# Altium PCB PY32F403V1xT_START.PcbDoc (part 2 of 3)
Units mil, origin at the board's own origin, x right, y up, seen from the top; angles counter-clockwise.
Board outline 1968.43 x 4717 mil, 2 copper layers (Top Layer, Bottom Layer), stack 21 mil thick; 171 components, 201 nets, 720 pads, 402 vias.
Unrouted connection lines stored in the file: 1.
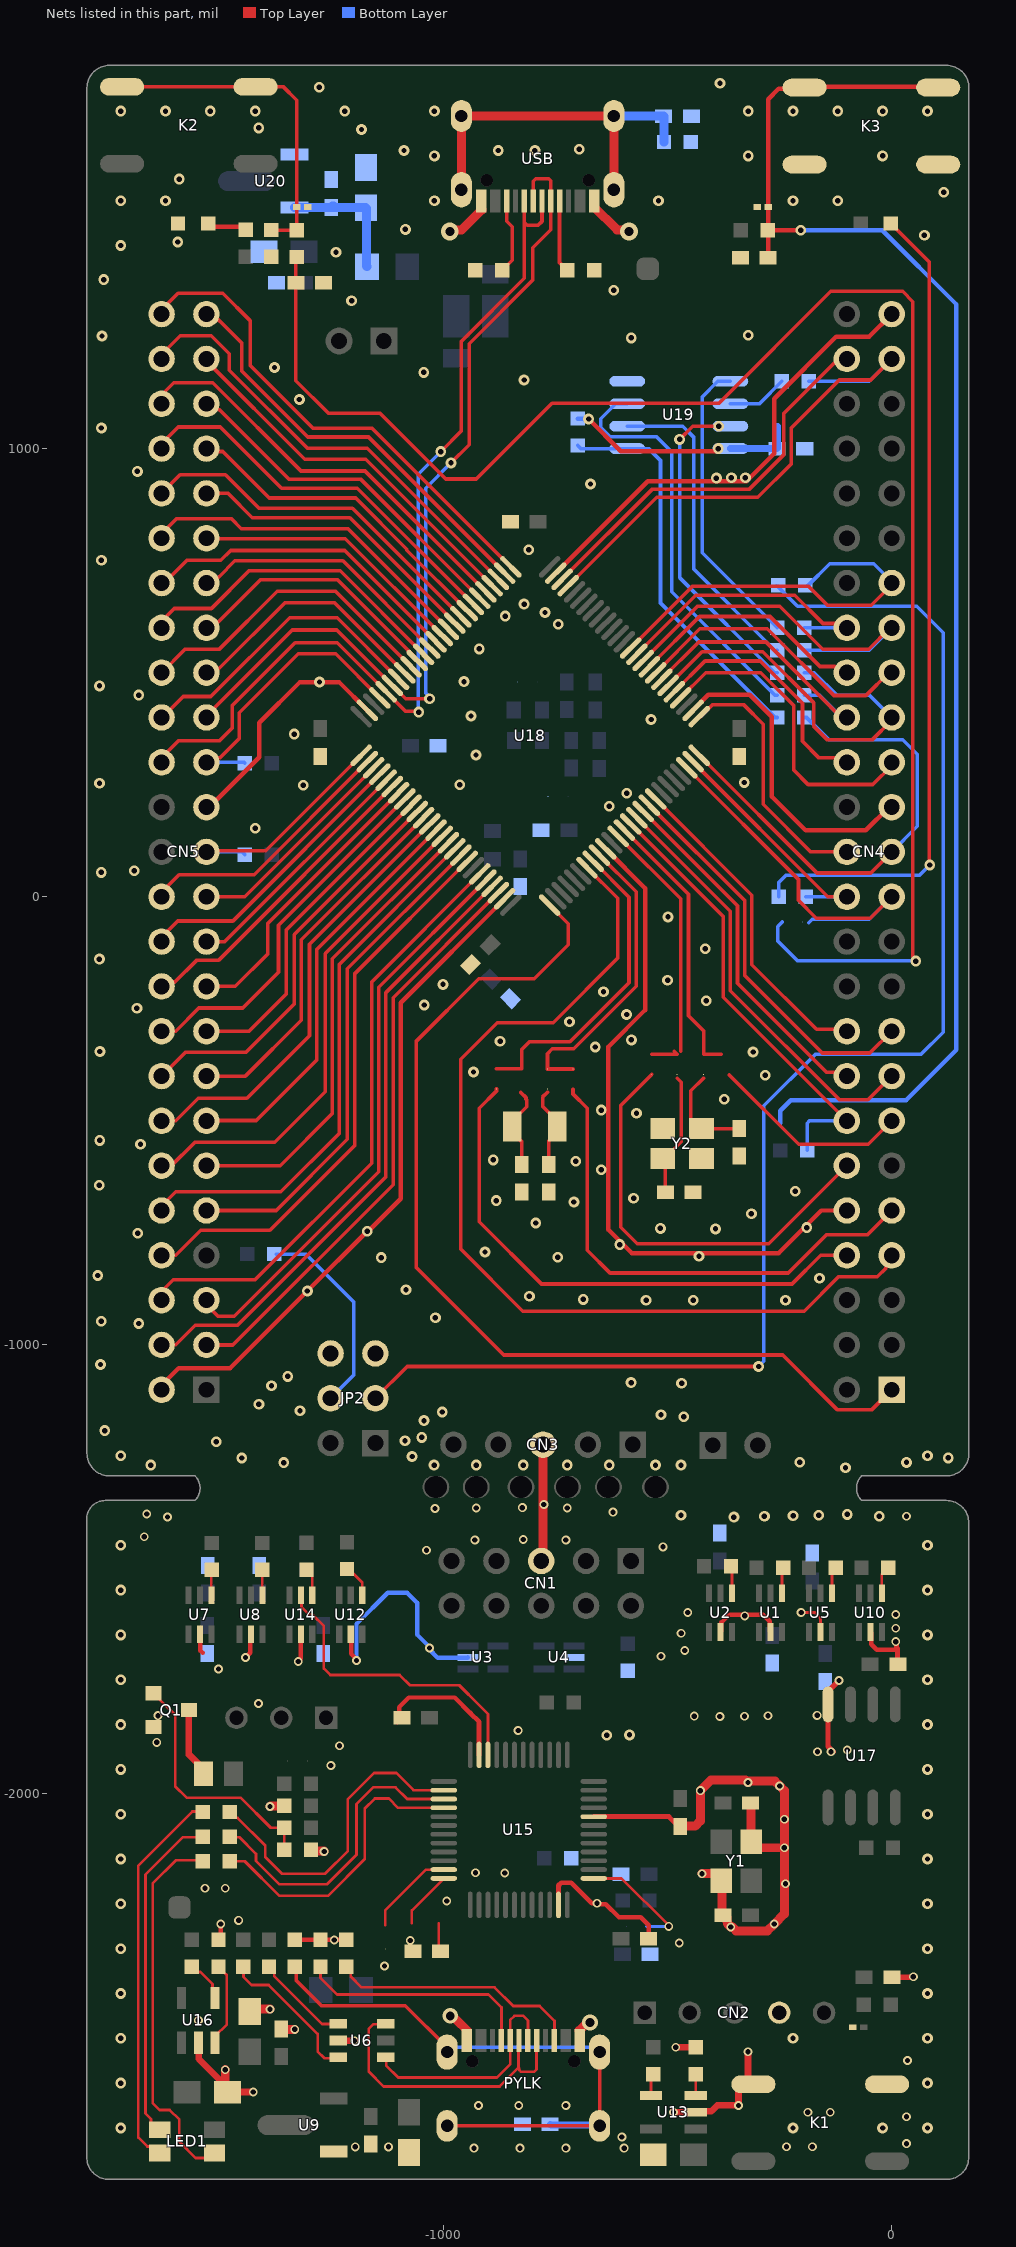
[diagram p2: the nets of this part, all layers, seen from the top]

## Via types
v1: diameter 24, hole 12, Top Layer to Bottom Layer, tented both sides, 230 vias
v2: diameter 19.68, hole 11.81, Top Layer to Bottom Layer, tented both sides, 116 vias
v3: diameter 19.68, hole 11.81, Top Layer to Bottom Layer, 37 vias
v4: diameter 35, hole 20, Top Layer to Bottom Layer, tented both sides, 11 vias
v5: diameter 40, hole 20, Top Layer to Bottom Layer, tented both sides, 6 vias
v6: diameter 30, hole 15, Top Layer to Bottom Layer, tented both sides, 2 vias

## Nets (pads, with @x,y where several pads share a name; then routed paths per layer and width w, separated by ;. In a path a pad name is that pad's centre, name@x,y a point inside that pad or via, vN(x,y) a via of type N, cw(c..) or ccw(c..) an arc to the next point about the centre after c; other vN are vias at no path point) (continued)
DIR_VCP_RX: U14.5 U15.22 | length 688.5
  Top Layer w6: U14.5@-1318.31,-1558.69 -1316.93,-1560.07 -1316.93,-1584.86 -1300.4,-1601.4 -1292.8,-1601.4 -1267,-1627.19 -1267,-1721.94 -1252.39,-1736.55 -1097.7,-1736.55 -1074.95,-1759.29 -964.82,-1759.29 -920.62,-1803.49 -900.9,-1823.21 U15.22@-900.9,-1914.68
F_CS: R47.1 R48.2 U19.1 | length 883.2
  Bottom Layer w8: R47.1@-700.5,1007 -693.5,1000 U19.1@-590,1000 -542.5,1000 -515.9,973.4 -515.9,655.34 -260.56,400 R48.2@-255,400
F_HOLD: R55.2 U19.7 | length 713.7
  Top Layer w8: v1(-473.3,1020.4) -443.8,1049.9 v1(-386,1049.9)
  Bottom Layer w8: v1(-473.3,1020.4) -473.3,712.53 -260.77,500 R55.2@-255,500
F_SCK: R49.2 U19.6 | length 135.7
  Bottom Layer w8: U19.6@-360,1100 -295,1100 R49.2@-245,1150
F_SI: R50.2 U19.5 | length 661.6
  Bottom Layer w8: U19.5@-360,1150 -387.8,1150 -422.61,1115.19 -422.61,767.61 R50.2@-255,600
F_SO: R52.2 U19.2 | length 714.4
  Bottom Layer w8: U19.2@-590,1050 -466.4,1050 -441.28,1024.88 -441.28,730.67 -260.61,550 R52.2@-255,550
F_VDD: C36.2 R46.2 R47.2 U19.8 | length 500.5
  Top Layer w10: v1(-676.21,1065.94) -604.64,994.37 -392.33,994.37 v1(-386.8,999.9)
  Bottom Layer w10: R47.2@-700.5,1067 -677.27,1067 v1(-676.21,1065.94)
  Bottom Layer w15: U19.8@-360,1000 C36.2@-256,1000 -255,1001 -255,1050
F_WP: R53.2 U19.3 | length 916.9
  Bottom Layer w8: U19.3@-590,1100 -615.7,1100 -649.25,1066.45 -649.25,1047.31 -627.94,1026 -524.5,1026 -491,992.5 -491,680.24 -260.76,450 R53.2@-255,450
GND: C1.1 C2.1 C3.1 C4.1 C5.1 C6.1 C7.1 C8.1 C9.1 C10.1 C11.1 C12.1 C13.1 C14.1 C15.1 C16.1 C17.1 C18.1 C19.1 C20.1 C21.1 C22.1 C23.1 C24.1 C25.1 C26.1 C27.1 C28.1 C29.1 C30.1 C31.2 C32.2 C33.2 C34.2 C35.1 C36.1 C41.1 C42.1 C43.1 C44.1 C45.1 C46.1 C47.1 C48.1 C49.1 CN1.5 CN2.4 CN3.3 CN4.10 CN4.27 CN4.49 CN5.2 CN5.27 JP2.5 JP2.6 K1.3 K1.4 K3.3 K3.4 LED_VDD*.2 PYLK.A1 PYLK.A12 PYLK.B1 PYLK.B12 Q1.2 R1.1 R3.2 R5.1 R8.2 R20.1 R21.1 R25.1 R28.2 R30.1 R33.2 R51.1 R56.1 R60.1 R61.2 R62.1 R63.1 U1.2 U2.2 U3.2 U4.2 U5.2 U6.2 U7.2 U8.2 U9.1 U10.2 U11.2 U12.2 U13.2 U14.2 U15.8 U15.23 U15.47 U16.2 U17.4 U18.10 U18.27 U18.49 U18.74 U18.99 U19.4 U20.1 U21.2 U22.2 USB.A1 USB.A12 USB.B1 USB.B12 Y1.2 Y1.4 Y2.2 Y2.4 | length 10026.1
  Top Layer w6: v2(-202,-1597) -172,-1597 -158.94,-1610.06 U5.2@-158.94,-1640.31
  Top Layer w10: CN5.2@-1639,-1100 -1590.6,-1051.6 -1475.7,-1051.6 v1(-1303.7,-879.6) v1(-1170.4,-746.3) -1167.83,-746.3 -1095.44,-673.91 -1095.44,-236.39 U18.99@-864.03,-4.98 ; U7.2@-1543.45,-1645.31 -1542.46,-1646.3 -1542.46,-1681.92 -1537.64,-1686.75 ; CN5.27@-1533.91,205.09 -1516.94,205.09 -1410.84,311.19 -1410.84,388.59 -1320.31,479.13 -1233.12,479.13 U18.74@-1169.82,415.82 ; R30.1@-1502,-2327 -1497,-2322 v2(-1497,-2292) ; C16.1@-1487,-2652 -1487,-2662 C16.1@-1482,-2667 ; v2(-1442,-1697.4) -1431.11,-1686.51 -1431.11,-1646.68 U8.2@-1429.74,-1645.31 ; C2.1@-1432,-2487 C2.1@-1427,-2482 ; C3.1@-1362,-2526 C3.1@-1361,-2527 ; R8.2@-1332,-2327 v2@-1243.05,-2327 ; v2(-1324.1,-1706.3) -1318.41,-1700.61 U14.2@-1318.41,-1645.41 ; R20.1@-1295.48,-2126.12 R20.1@-1293.96,-2124.6 ; v2(-1243.9,-2327.85) v2@-1243.05,-2327 ; R3.2@-1217,-2327 v2@-1243.05,-2327 ; U12.2@-1206.88,-1645.31 -1205.59,-1646.6 -1205.59,-1689.38 -1195.17,-1699.8 -1195.17,-1705.17 v2@-1197,-1707 ; C21.1@-1103.64,-1842 -1093.64,-1832 C21.1@-1093,-1832 -1099.05,-1825.95 -1099.05,-1807.86 -1077.77,-1786.58 -975.02,-1786.58 -940.18,-1821.42 ; C17.1@-1068.41,-2352.5 C17.1@-1067.41,-2351.5 ; PYLK.A1@-953.69,-2552.11 PYLK.B12@-941.88,-2552.11 ; U18.49@-749.46,722.05 -544.41,927.1 -323.94,927.1 -262.21,988.83 -262.21,1111.26 -123.46,1250 -50,1250 CN4.49@0,1300 ; PYLK.B1@-701.72,-2552.11 PYLK.A12@-689.91,-2552.11 ; v2@-657.53,-2248.44 v2@-657.4,-2248.31 ; v2@-655.39,-2247.98 -637.64,-2247.98 -608.43,-2277.2 -559.93,-2277.2 -542.09,-2295.05 C20.1@-542.13,-2324.41 ; U18.10@-638.1,106.82 -550.31,19.02 -550.31,-252.67 -632,-334.36 -632,-743.04 -580.04,-795 -251.97,-795 -156.97,-700 CN4.10@-100,-700 ; U18.27@-443.23,416.79 -409.01,451 -317,451 -267.67,401.67 -267.67,223.66 -192.25,148.24 -57.76,148.24 -6,200 CN4.27@0,200 ; U2.2@-382.74,-1641.25 U2.2@-381.79,-1640.31 -379.9,-1638.42 -379.9,-1619.05 -362.85,-1602 v2@-326.98,-1602 ; v2(-327.8,-1604.4) -326.98,-1603.58 v2@-326.98,-1602 ; U1.2@-270.36,-1640.31 -272.25,-1638.42 -272.25,-1616.75 -287,-1602 v2@-326.98,-1602 ; U10.2@-47.51,-1640.31 -45.62,-1642.2 -45.62,-1668.04 -33.39,-1680.28 13.04,-1680.28
  Top Layer w11: -940.18,-1821.42 -920.58,-1841.02 U15.23@-920.58,-1914.68 ; U15.47@-743.42,-2249.32 -743.42,-2206.09 -737.26,-2199.93 -714.92,-2199.93 -669.13,-2245.72 v2(-657.65,-2245.72) ; U15.8@-664.68,-2052.47 -497.06,-2052.47 -475.53,-2074 C22.1@-471.88,-2074
  Top Layer w12: Q1.2@-1646.8,-1852.2 Q1.2@-1641.99,-1857.01 ; v2(-135.29,-1907.73) -130.16,-1907.73 -142,-1895.89 U17.4@-142,-1802 -142,-1773.12 -117.61,-1748.73 v2(-117.61,-1748.49) ; C6.1@0.2,-2410.8 47.2,-2410.8 v2(48.4,-2409.6) ; v2(9.2,-1662) 10.67,-1663.47 10.67,-1675.47 13.04,-1677.84 13.04,-1680.28 13.04,-1711.04 C18.1@14,-1712
  Top Layer w15: U16.2@-1547.52,-2557.52 -1546.09,-2558.96 -1546.09,-2592.91 C16.1@-1487,-2652 ; C16.1@-1482,-2667 v2(-1424.44,-2667) ; U6.2@-1226.34,-2551.95 -1224.76,-2553.53 -1223.71,-2552.48 v2(-1198.92,-2552.48) ; v2(-487,-2712) U13.2@-437,-2712 -434.84,-2709.84 -402.34,-2709.84 -388.77,-2696.26 v2@-342.74,-2696.26 ; v2(-482,-2567) R25.1@-437,-2567 ; v2(-342,-2697) -342,-2652.56 -330.74,-2641.3 -320.45,-2641.3 v2(-320.45,-2577)
  Top Layer w20: C16.1@-1487,-2652 v2(-1487,-2617) ; C2.1@-1427,-2482 v2(-1387,-2482) ; v2(-1387.17,-2029.71) -1386.41,-2028.96 -1355.83,-2028.96 R21.1@-1355.07,-2028.2 ; C3.1@-1361,-2527 v2(-1332,-2527) ; R20.1@-1293.96,-2124.6 -1293.96,-2124.88 -1289.48,-2129.36 -1267.06,-2129.36 v2(-1266.3,-2130.13) ; v4(-984.92,-2497) -980.87,-2497 -973.37,-2504.5 -972.28,-2504.5 -946.1,-2530.69 PYLK.B12@-946.1,-2531.04 ; v5@-981.85,1482.73 -976.76,1487.83 -959.25,1487.83 -914.31,1532.77 USB.B1@-914.31,1533.34 ; CN1.5@-782,-1482 CN1.5@-774.53,-1474.53 ; CN1.5@-777.74,-1477.74 CN3.3@-777.74,-1222.44 ; PYLK.B1@-697.5,-2530.08 -680.26,-2512.84 -674.34,-2512.84 v4(-673.29,-2511.8) ; USB.B12@-665.71,1540.9 -612.63,1487.83 -589.97,1487.83 v5(-586.15,1484) ; C22.1@-476.88,-2065 -471.88,-2070 C22.1@-471.88,-2074 -471.59,-2073.72 -438.59,-2073.72 -426.88,-2062 v2(-426.88,-1994.43) -403.05,-1970.59 -326.59,-1970.59 v2(-320.74,-1976.45) -319.65,-1976.45 -316.55,-1973.35 -260.53,-1973.35 v2(-249.97,-1983.9) -239.42,-1994.46 v2(-239.42,-2058.15) -239.42,-2121.87 -239.42,-2269.54 v2(-261.88,-2292) -277.15,-2307.27 -347.11,-2307.27 v2@-357.36,-2297.02 ; v2(-423.02,-2179.71) -395.94,-2179.71 Y1.2@-380.34,-2195.31 -378.61,-2197.04 -378.61,-2270.27 C19.1@-376.88,-2272 -372.88,-2272 -367.88,-2277 -367.88,-2286.5 -366.63,-2287.75 ; -366.63,-2291.37 v2(-359.17,-2298.82) ; C25.1@-314.88,-2022 -314.15,-2022.73 -314.15,-2107.96 Y1.4@-313.41,-2108.69 -300.26,-2121.84 v2(-239.45,-2121.84)
  Bottom Layer w6: v2@-1197.74,-1704.17 v2(-1194.11,-1704.17)
  Bottom Layer w10: v2(-1194.11,-1704.17) -1194.11,-1622.51 -1124.54,-1552.94 -1081.28,-1552.94 -1059,-1575.22 -1059,-1646.21 -1031.11,-1674.1 v2(-1031.11,-1676.11) ; v2@-1032,-1679 -1013.28,-1697.72 -946.19,-1697.72 U3.2@-945.46,-1697
  Bottom Layer w20: CN1.5@-782,-1482 CN1.5@-776,-1476 ; CN3.3@-777.74,-1222.44 CN3.3@-776,-1224.18 ; CN3.3@-776,-1222.44 CN3.3@-776,-1219.06
  other v1: -1720.22,-2747 -220.22,-2747 -20.22,-2747 79.78,-2747 -1720.22,-2647 79.78,-2647 -1720.22,-2547 -220.22,-2547 79.78,-2547 -1720.22,-2447 79.78,-2447 -1720.22,-2347 79.78,-2347 -1720.22,-2247 79.78,-2247 -1720.22,-2147 79.78,-2147 -1720.22,-2047 79.78,-2047 -1720.22,-1947 79.78,-1947 -636,-1871 -585,-1870 -1720.22,-1847 79.78,-1847 -1720.22,-1747 79.78,-1747 -1720.22,-1647 79.78,-1647 -1720.22,-1547 79.78,-1547 -1720.22,-1447 79.78,-1447 -352,-1384 -284,-1382 -28,-1382 -220,-1381 -470,-1380 -163,-1380 -99,-1378 -103,-1274 -1653.43,-1268 -1021,-1268 -927,-1268 -822,-1268 -724,-1268 -630,-1268 -527,-1268 -470,-1268 -1356.5,-1262.4 -205.3,-1261.87 33,-1262 -1450,-1252.1 126,-1252 -1070,-1249 -1720.22,-1247 79.78,-1247 -1507.1,-1216.1 -1085.9,-1213.5 -1048.3,-1206.3 -1756,-1191 -1043.4,-1168.8 -463.91,-1160.44 -514.6,-1155.9 -1002.7,-1149.6 -1320.22,-1147 -1411.9,-1132.5 -1383.7,-1090.8 -468.71,-1085.34 -581.51,-1084.04 -1347.6,-1070.2 -1765.2,-1043.5 -1680,-952 -1763.9,-947.1 -1018,-939.5 -548,-900.49 -443,-900.49 -236.91,-900.49 -688.3,-898.3 -808.3,-891.1 -1083.6,-876.8 -161,-851 -1771.4,-845 -1138.7,-805.1 -744.97,-804.36 -429.9,-801.9 -907.4,-792.6 -607,-776 -1682,-751 -393,-741 -516,-740 -189.7,-738.2 -794.1,-727.9 -313,-707 -709.07,-681.16 -882.57,-677.86 -575.8,-672.4 -215,-657 -1768,-643.8 -648,-609 -705.17,-590.26 -889.17,-587.06 -1676,-552 -1767,-543.6 -569.3,-483.1 -648,-476 -373.8,-451.7 -282.3,-398 -933.2,-391.1 -309.2,-346.3 -1766.7,-345.2 -661.6,-335.3 -873.7,-322.3 -580.8,-319.4 -719,-279 -591.5,-262.6 -1684,-249 -1043.1,-241.4 -414,-232 -643,-212 -1001.1,-195.6 -500,-186 -1767.8,-139 -416,-116 -499,-45 -1763.7,54.4 -1690,58 -1420.22,153 -630.1,202.1 -591.4,231.1 -1313,249 -963.7,249.7 -1767.4,253.4 -329,255 -927.4,316.4 -1333,363 -536.85,395.59 -938.6,403.2 -1680,450 -1767.4,470.5 -1276.72,479.13 -954.3,480.1 -920.22,553 -744.1,608.3 -862.1,626.2 -773.5,634.2 -820.22,653 -1763.3,751.1 -810,774 -672,921 -391.1,934.1 -357.6,934.7 -326.45,934.81 -1683,949 -1763.3,1045.9 -1321.51,1109.49 -820.22,1153 -1043.9,1170 -1377,1181 -580.95,1246.89 -1761.9,1251.2 -320.22,1253 -1205,1330 -620.22,1353 -1758,1377 -1239.9,1438.1 -1720.22,1453 -1593,1461 73,1476 -1085,1489 -1720.22,1553 -1620.22,1553 -1020.22,1553 -520.22,1553 -220.22,1553 -120.22,1553 116,1572 -1589.4,1601.2 -1020.22,1653 -320.22,1653 -20.22,1653 -1088,1665 -878,1665 -796,1665 -697,1668 -1183,1712 -1412.2,1715.5 -1720.22,1753 -1620.22,1753 -1520.22,1753 -1420.22,1753 -1220.22,1753 -1020.22,1753 -320.22,1753 -220.22,1753 -120.22,1753 -20.22,1753 79.78,1753 -1277,1806 -383,1815
  other v2: -932,-2792 -829.5,-2792 -727,-2792 -597,-2792 -234.75,-2789 -177,-2789 33,-2782 -602,-2767 33,-2722 -187,-2712 -137,-2712 -922,-2697 -832,-2697 -727,-2697 35.4,-2596.4 -1547,-2507 -1532,-2212 -1487,-2212 -236.88,-2202 -1639.7,-1886.66 -1637,-1827 -514.65,-1694.43 -455.06,-1597.05 -1038,-1458 -930,-1435 -727,-1435 -822,-1434 -1616,-1384 33,-1382 -1662,-1377 -622,-1373 -1019,-1365 -927,-1364 -724,-1364 -824,-1363 -776,-1356
  other v3: -1196.77,-2789.27 -1122.52,-2789.28 -1131.7,-2385.8 -473.95,-2334.23 -1074.25,-2328.85 -1457.07,-2283.82 -992.57,-2240.41 -863.37,-2178.06 -928.53,-2177.5 -1251.29,-1938.32 -165.67,-1907.47 -99.24,-1903.62 -1232.14,-1894.38 -833.45,-1860.42 -383.41,-1828.94 -328.42,-1828.55 -440.34,-1828.16 -275.76,-1827.37 -166.33,-1826.45 -1413,-1800 -1502,-1723 -461.71,-1681.53 -469.81,-1643.1 9.2,-1632.22 9.2,-1601.35 -510.41,-1450.46 -1667.7,-1427.9
  other v5: -986,1484
L_USB_CN_DM: PYLK.A7 PYLK.B7 U6.4 | length 509.8
  Top Layer w6: U6.4@-1128.85,-2589.4 -1127.82,-2590.43 -1127.82,-2607.54 -1100.96,-2634.4 -880.64,-2634.4 -850.93,-2604.7 PYLK.B7@-850.93,-2552.51 ; PYLK.B7@-851.42,-2552.02 -851.42,-2506.42 -842,-2497 -822,-2497 -811.31,-2507.69 -811.31,-2551.46 PYLK.A7@-811.96,-2552.11
L_USB_CN_DP: PYLK.A6 PYLK.B6 U6.6 | length 674.3
  Top Layer w6: U6.6@-1128.85,-2514.6 -1129.74,-2515.49 -1156.61,-2515.49 -1166.65,-2525.53 -1166.65,-2621.6 -1133.78,-2654.47 -874.73,-2654.47 -834.45,-2614.19 -832.05,-2611.79 ; -832.54,-2612.28 -832.54,-2553.01 PYLK.A6@-831.64,-2552.11 ; -831.25,-2617.39 -831.25,-2614.19 ; -830.69,-2617.96 -826.95,-2621.69 -797.94,-2621.69 -792.7,-2616.45 -792.7,-2552.54 PYLK.B6@-792.27,-2552.11
LED_BLUE: R9.2 U15.28 | length 674.3
  Top Layer w6: R9.2@-1477,-2152 -1443.49,-2152 -1366.3,-2229.19 -1257.44,-2229.19 -1175.67,-2147.42 -1175.67,-2034.59 -1153.08,-2012 -1122,-2012 -1101.21,-2032.79 U15.28@-999.32,-2032.79
LED_GREEN: R6.2 U15.26 | length 726.2
  Top Layer w6: R6.2@-1477,-2042 -1464,-2055 -1459.6,-2055 -1397.73,-2116.87 -1397.73,-2142.73 -1360.59,-2179.87 -1264.73,-2179.87 -1213.52,-2128.66 -1213.52,-2013.52 -1155.25,-1955.25 -1105.09,-1955.25 -1066.93,-1993.42 U15.26@-999.32,-1993.42
LED_RED: R4.2 U15.27 | length 697.6
  Top Layer w6: R4.2@-1477,-2097 -1475.6,-2098.4 -1455.51,-2098.4 -1418.4,-2135.52 -1418.4,-2150.95 -1365.78,-2203.57 -1260.48,-2203.57 -1194.32,-2137.41 -1194.32,-2024.32 -1157,-1987 -1107,-1987 -1080.9,-2013.1 U15.27@-999.32,-2013.1
NetC1_2: C1.2 PYLK.1 PYLK.2 PYLK.3 PYLK.4 R8.1 | length 1406.9
  Top Layer w8: R8.1@-1332,-2387 -1328.71,-2390.29 -1328.71,-2418.13 -1272.36,-2474.48 -1085.03,-2474.48 -991.88,-2567.63 PYLK.1@-991.88,-2577.71 ; PYLK.3@-991.88,-2742.27 PYLK.4@-651.72,-2742.27 PYLK.2@-651.72,-2577.71
  Bottom Layer w8: PYLK.1@-980.96,-2566.79 PYLK.2@-662.64,-2566.79
  Bottom Layer w15: C1.2@-762,-2739 -760.36,-2740.64 -653.36,-2740.64 PYLK.4@-651.72,-2742.27
  Bottom Layer w20: PYLK.1@-991.88,-2577.71 PYLK.1@-980.96,-2566.79 ; PYLK.2@-662.64,-2566.79 PYLK.2@-651.72,-2577.71
NetC17_2: C17.2 R31.2 | length 64.1
  Top Layer w6: -1010.79,-2290.25 -1010.79,-2348.12 C17.2@-1006.41,-2352.5
NetC27_2: C27.2 R38.1 Y2.3 | length 281.1
  Top Layer w8: C27.2@-504.8,-659.7 -504.8,-590.47 Y2.3@-511.11,-584.16 -507.17,-584.16 -469.45,-546.44 -469.45,-414.04 -478.8,-404.69
NetC30_2: C30.2 R41.1 Y2.1 | length 221.4
  Top Layer w8: -419.8,-404.7 -448.25,-433.15 -448.25,-492.93 -448.05,-493.13 -448.05,-497.61 -428.43,-517.24 Y2.1@-424.49,-517.24 -340.34,-517.24 C30.2@-339.8,-516.7
NetC32_1: C32.1 R44.2 Y3.1 | length 188.4
  Top Layer w8: -828,-436 -816,-448 -816,-451.28 -814.59,-452.69 -814.59,-468.6 -846.19,-500.2 -846.19,-513 -846.19,-525.79 -825,-546.98 C32.1@-825,-597
NetC35_2: C35.2 R45.2 Y3.2 | length 187.2
  Top Layer w8: -768,-436 -778.94,-446.94 -778.94,-467.07 -745.8,-500.2 -745.8,-513 -745.8,-525.79 -765,-544.99 C35.2@-765,-597
NetC45_2: C45.2 K3.1 K3.2 R57.2 R58.1 U21.1 | length 3376.6
  Top Layer w10: C45.2@-275.7,1425.3 R57.2@-275.7,1485.8 ; v1(-202.8,1487.1) -274.4,1487.1 R57.2@-275.7,1485.8 ; K3.2@105,1807.7 -193,1807.7 -198.08,1802.62 -252.38,1802.62 -275.7,1779.3 U21.1@-275.7,1539 -275.7,1488 R57.2@-276.8,1486.9 R57.2@-275.7,1485.8
  Bottom Layer w10: -248.55,-505 -248.55,-477.55 -225,-454 32,-454 144.5,-341.5 144.5,1321.5 -21.1,1487.1 v1(-202.8,1487.1)
NetC46_2: C46.2 C47.2 F2.2 U20.3 | length 296.1
  Bottom Layer w20: U20.3@-1332.51,1537.74 -1332.18,1538.07 -1250.63,1538.07 C47.2@-1250.3,1538.4 -1247.6,1541.1 -1245.6,1541.1 -1245.6,1538.7 -1245.3,1538.4 -1174.1,1538.4 C46.2@-1173,1537.3 -1171.84,1536.14 -1171.84,1407.16 F2.2@-1170.68,1406
NetC48_2: C48.2 R59.1 R70.1 | length 3773
  Top Layer w8: R70.1@-1329.6,1427.3 C48.2@-1329.6,1369.9 -1329.6,1151.51 -1256.78,1078.7 -1141.56,1078.7 -994.96,932.1 -927.1,932.1 -757.8,1101.4 -385.4,1101.4 -136,1350.8 24.4,1350.8 47.3,1327.89 47.3,-133.1 53.44,-139.23 v1(53.44,-143.56)
  Bottom Layer w8: R59.1@-244.05,-56.3 -254.25,-66.5 -254.25,-98.85 -209.9,-143.2 v1@53.08,-143.2
NetC49_2: C49.2 R63.2 USB.1 USB.2 USB.3 USB.4 | length 838.1
  Top Layer w20: USB.2@-960.08,1577.52 USB.4@-960.08,1742.08 USB.3@-619.92,1742.08 USB.1@-619.92,1577.52
  Bottom Layer w20: USB.3@-619.92,1742.08 -619.38,1741.54 -509.54,1741.54 C49.2@-509,1741 -508.5,1740.5 -508.5,1684.5 R63.2@-508,1684
NetCN4_8: CN4.8 R66.2 | length 1216.6
  Top Layer w8: R66.2@-881.8,-428.7 -881.8,-433.5 -920.1,-471.8 -920.1,-725.4 -781.5,-864 -222.43,-864 -158.43,-800 CN4.8@-100,-800
NetCN4_9: CN4.9 R67.2 | length 1130.8
  Top Layer w8: R67.2@-711.13,-429.18 -711.13,-440.07 -679.4,-471.8 -679.4,-788.5 -628.4,-839.5 -231.1,-839.5 -145.4,-753.8 -53.8,-753.8 CN4.9@0,-700
NetCN4_12: CN4.12 R68.1 | length 961.5
  Top Layer w8: R68.1@-535.3,-396.45 -604.6,-465.75 -604.6,-737.1 -567.5,-774.2 -274.2,-774.2 CN4.12@-100,-600
NetCN4_13: CN4.13 R69.1 | length 449
  Top Layer w8: R69.1@-362.9,-397 -207.5,-552.4 -52.4,-552.4 CN4.13@0,-500
NetJP2_3: JP2.3 R42.2 | length 3246.1
  Top Layer w8: JP2.3@-1152,-1119 -1081,-1048 v1(-297,-1048)
  Bottom Layer w8: v1(-297,-1048) -285.24,-1036.24 -285.24,-466.63 -170.11,-351.5 65.5,-351.5 115,-302 115,589 56,648 -210,648 -256,694 R42.2@-257.5,694
NetJP2_4: JP2.4 R43.1 | length 453.7
  Bottom Layer w8: R43.1@-1373.5,-798 -1306.2,-798 -1200.2,-904 -1200.2,-1067.2 JP2.4@-1252,-1119
NetK2_3: K2.3 K2.4 R60.2 R70.2 U22.1 | length 746.9
  Top Layer w8: K2.4@-1715,1807.7 -1358.18,1807.7 -1327.61,1777.12 U22.1@-1327.61,1539 -1327.61,1487.49 R70.2@-1327.8,1487.3 -1384.2,1487.3 R60.2@-1384.6,1487.7
NetLED1_2: LED1.2 R9.1 | length 846.1
  Top Layer w6: R9.1@-1537,-2152 -1539.33,-2149.67 -1596.67,-2149.67 -1649,-2202 -1649,-2691 -1633.2,-2706.8 -1611.14,-2706.8 -1589.47,-2728.47 -1589.47,-2777.84 -1553.18,-2814.13 -1521.92,-2814.13 LED1.2@-1510.98,-2803.18
NetLED1_3: LED1.3 R6.1 | length 884.3
  Top Layer w6: LED1.3@-1652.72,-2803.48 LED1.3@-1638.02,-2818.18 ; LED1.3@-1633.02,-2803.18 -1647.72,-2788.48 -1660.91,-2788.48 -1681,-2768.39 -1681,-2161.66 -1560.41,-2041.07 -1537.93,-2041.07 R6.1@-1537,-2042
NetLED1_4: LED1.4 R4.1 | length 755.1
  Top Layer w6: LED1.4@-1640.34,-2763.5 -1652.64,-2751.19 -1652.64,-2727.26 -1665,-2714.91 -1665,-2181.66 -1581.61,-2098.27 -1538.27,-2098.27 R4.1@-1537,-2097
NetLED_PA1_2: LED_PA1.2 R54.1 | length 1851.9
  Top Layer w8: LED_PA1.2@-2,1502 84.23,1415.77 v1@84.23,71
  Bottom Layer w8: R54.1@-252,0 -252,32 -236,48 62,48 v1(85,71)
NetLED_VDD*_1: LED_VDD*.1 R65.1 | length 89.8
  Top Layer w10: LED_VDD*.1@-1525,1502 -1518.07,1495.07 -1448.07,1495.07 R65.1@-1441,1488
NetPYLK_A5: PYLK.A5 R1.2 | length 530.1
  Top Layer w6: R1.2@-1274.51,-2387.01 -1274.51,-2412.18 -1237.49,-2449.21 -899.42,-2449.21 -870.76,-2477.87 PYLK.A5@-870.76,-2551.86
NetPYLK_B5: PYLK.B5 R3.1 | length 566.5
  Top Layer w6: R3.1@-1217,-2387 -1206.69,-2397.31 -1206.69,-2409.66 -1183.15,-2433.2 -885.89,-2433.2 -844.34,-2474.76 -785.45,-2474.76 -752.29,-2507.92 -752.29,-2551.5 PYLK.B5@-752.9,-2552.11
NetQ1_1: Q1.1 R19.1 R20.2 | length 559
  Top Layer w6: Q1.1@-1647,-1777.2 -1645.03,-1777.2 -1633.28,-1788.94 -1633.28,-1790.77 -1598.54,-1825.51 -1598.54,-1984.66 -1573.14,-2010.06 -1452.55,-2010.06 -1385.39,-2077.22 R19.1@-1355.47,-2077.22 ; R20.2@-1355.48,-2126.12 R19.1@-1355.48,-2077.23
NetQ1_3: Q1.3 R15.1 | length 166.5
  Top Layer w6: Q1.3@-1571.51,-1817.85 Q1.3@-1568.26,-1814.6 ; R15.1@-1535.46,-1957 R15.1@-1535.46,-1951.09
  Top Layer w15: Q1.3@-1568.26,-1814.6 -1568.26,-1913.72 -1535.46,-1946.51 R15.1@-1535.46,-1957
NetR2_1: R2.1 U1.4 | length 57.9
  Top Layer w6: U1.4@-244.77,-1553.69 -244.77,-1499.98 R2.1@-241.79,-1497
NetR7_1: R7.1 U2.4 | length 57.8
  Top Layer w6: R7.1@-358.94,-1497 -356.2,-1499.73 U2.4@-356.2,-1553.69
NetR10_1: R10.1 U5.4 | length 60.3
  Top Layer w6: U5.4@-133.34,-1553.69 -133.34,-1505.7 R10.1@-124.65,-1497
NetR11_1: R11.1 U6.3 | length 332.9
  Top Layer w6: R11.1@-1447,-2387 -1446.23,-2387.77 -1446.23,-2410.31 -1428.59,-2427.95 -1390.2,-2427.95 -1280.76,-2537.39 -1280.76,-2576.13 -1265.37,-2591.52 -1237.26,-2591.52 U6.3@-1235.47,-2589.72
NetR12_1: R12.1 U6.1 | length 227.7
  Top Layer w6: R12.1@-1388.25,-2382 -1377.85,-2392.4 -1377.85,-2408.32 -1271,-2515.17 U6.1@-1225.03,-2515.17
NetR13_1: R13.1 U7.4 | length 59
  Top Layer w6: R13.1@-1523.45,-1502 -1517.86,-1507.59 U7.4@-1517.86,-1558.69
NetR14_1: R14.1 U8.4 | length 60.8
  Top Layer w6: R14.1@-1416.06,-1501.98 R14.1@-1406.18,-1511.86 ; U8.4@-1404.14,-1558.69 R14.1@-1404.14,-1511.88
NetR18_1: R18.1 U10.4 | length 62.7
  Top Layer w6: U10.4@-21.92,-1553.69 -21.92,-1511.41 R18.1@-7.51,-1497
NetR22_1: R22.1 U12.4 | length 75.3
  Top Layer w6: R22.1@-1215.37,-1499.89 -1211.38,-1499.89 -1181.29,-1529.97 U12.4@-1181.29,-1558.69
NetR24_2: R24.2 U13.4 | length 49.6
  Top Layer w6: U13.4@-537,-2674.5 -537,-2632 R24.2@-532,-2627
NetR25_2: R25.2 U13.3 | length 47.5
  Top Layer w6: U13.3@-437,-2674.5 R25.2@-437,-2627
NetR26_1: R26.1 U14.4 | length 62.8
  Top Layer w6: R26.1@-1305.8,-1501.3 -1292.72,-1514.38 U14.4@-1292.72,-1558.69
NetR27_2: R27.2 U15.1 | length 262.3
  Top Layer w6: U15.1@-664.68,-2190.27 -602.82,-2190.27 -497.3,-2295.79 v3(-497.3,-2297.2)
  Bottom Layer w6: R27.2@-546.97,-2297.57 -497.67,-2297.57 v3(-497.3,-2297.2)
NetR29_2: R29.2 U16.4 | length 96.1
  Top Layer w6: R29.2@-1562,-2387 -1550,-2399 -1542.56,-2399 -1515.5,-2426.06 -1515.5,-2451 U16.4@-1509.5,-2457
NetR30_2: R30.2 U16.3 | length 188.5
  Top Layer w6: U16.3@-1509.5,-2557 -1509.5,-2542 -1483.44,-2515.94 -1483.44,-2406.32 -1490,-2399.76 -1490,-2399 R30.2@-1502,-2387
NetR31_1: R31.1 U15.36 | length 129.6
  Top Layer w6: -1070.79,-2290.25 -1070.79,-2261.74 U15.36@-999.32,-2190.27
NetR33_1: R33.1 U15.35 | length 201.4
  Top Layer w6: -1130.04,-2294.6 -1130.04,-2261.62 -1039,-2170.58 U15.35@-999.32,-2170.58
NetR61_1: R61.1 USB.A5 | length 160.6
  Top Layer w8: USB.A5@-741.21,1551.5 -741.21,1415.21 R61.1@-724,1398
NetR62_2: R62.2 USB.B5 | length 168.4
  Top Layer w8: R62.2@-869,1398 -846.51,1420.49 -846.51,1494.6 -858.9,1507 USB.B5@-858.9,1551.92
NRST: CN4.14 R40.2 R58.2 U18.14 | length 1013.9
  Top Layer w8: U18.14@-582.42,162.5 -376.03,-43.89 -376.03,-223.97 CN4.14@-100,-500
  Bottom Layer w8: R40.2@-188.55,-566 -188.55,-505 -183.55,-500 CN4.14@-100,-500
OSC_IN: R38.2 R68.2 U18.12 | length 602.3
  Top Layer w8: U18.12@-610.26,134.66 -471,-4.6 -471,-344.2 ; R68.2@-535.27,-351.67 R38.2@-478.77,-351.66 -485.34,-345.1
OSC_OUT: R41.2 R69.2 U18.13 | length 612.3
  Top Layer w8: U18.13@-596.34,148.58 -453.3,5.53 -453.3,-265.6 -419.77,-299.13 R41.2@-419.77,-351.67 -380.83,-351.67
PA0: CN4.23 R59.2 U18.23 | length 852
  Top Layer w8: U18.23@-457.15,287.77 -208,38.62 -208,-8.06 -168.34,-47.72 -47.72,-47.72 CN4.23@0,0
  Bottom Layer w8: -184.87,-57.77 -177.2,-50.1 -50.1,-50.1 CN4.23@0,0
PA1: CN4.24 R54.2 U18.24 | length 560.9
  Top Layer w8: U18.24@-443.23,301.69 -443.23,300.57 -142.66,0 CN4.24@-100,0
  Bottom Layer w8: R54.2@-192,0 CN4.24@-100,0
PA2: CN4.25 R48.1 U18.25 | length 1085.1
  Top Layer w8: U18.25@-429.31,315.61 -166.7,53 -47,53 CN4.25@0,100
  Bottom Layer w8: R48.1@-195,400 -189.94,400 -139.94,350 25,350 57,318 57,157 CN4.25@0,100
PA3: CN4.26 U18.26 | length 580.8
  Top Layer w8: U18.26@-429.31,401.91 -426.61,401.9 -400.54,427.98 -329.54,427.98 -286.84,385.27 -286.84,206.25 -180.58,100 CN4.26@-100,100
PA4: CN4.29 U18.29 | length 706.9
  Top Layer w8: U18.29@-471.06,444.11 -415.17,500 -292,500 -218.17,426.17 -218.17,282.09 -186.54,250.47 -41.97,250.47 0,292.44 CN4.29@0,300
PA5: CN4.30 U18.30 | length 556.8
  Top Layer w8: U18.30@-484.85,457.58 -416.43,526 -293,526 -199,432 -199,346.64 -162.13,309.77 -109.77,309.77 CN4.30@-100,300
PA6: CN4.31 R55.1 U18.31 | length 902.8
  Top Layer w8: U18.31@-498.55,471.5 -423.05,547 -288,547 -174.32,433.32 -174.32,381.13 -143.16,349.96 -43.74,349.96 0,393.71 CN4.31@0,400
  Bottom Layer w8: R55.1@-195,500 -172.79,500 -122.79,450 -50,450 CN4.31@0,400
PA7: CN4.32 R53.1 U18.32 | length 632.3
  Top Layer w8: U18.32@-512.83,486.1 -430.58,568.35 -280.61,568.35 -112.26,400 CN4.32@-100,400
  Bottom Layer w8: R53.1@-195,450 -161.78,450 -111.78,400 CN4.32@-100,400
PA8: CN5.34 U18.67 | length 711.8
  Top Layer w8: CN5.34@-1639,500 CN5.34@-1629,500 -1577.16,551.82 -1500.7,551.82 -1370.64,681.89 -1241.01,681.89 U18.67@-1072.38,513.26
PA9: CN5.33 U18.68 | length 582.4
  Top Layer w8: CN5.33@-1539,500 -1529.23,509.77 -1500.04,509.77 -1353.58,656.23 -1243.2,656.23 U18.68@-1086.3,499.34
PA10: CN5.32 U18.69 | length 676.4
  Top Layer w8: CN5.32@-1627.64,400 -1580.87,446.77 -1519.06,446.77 -1343.23,622.61 -1237.4,622.61 U18.69@-1100.22,485.42
PA11: CN5.31 U18.70 USB.A7 USB.B7 | length 2002.3
  Top Layer w8: CN5.31@-1528.35,404.53 -1337.58,595.3 -1237.94,595.3 U18.70@-1114.14,471.5 -1084.28,441.64 v1@-1031.36,441.64 ; v1(-983.4,968.1) -942.87,1008.63 -942.87,1234.13 -801,1376 -801,1448 -760.42,1488.58 USB.B7@-760.47,1551.92 ; USB.A7@-799.84,1551.92 -799.84,1596.16 -794,1602 -765.16,1602 -760.47,1597.31 USB.B7@-760.47,1551.92
  Bottom Layer w8: v1(-1031,442) -1031,445.84 -1039.84,454.69 -1039.84,911.66 v1(-983.4,968.1)
PA12: CN5.30 U18.71 USB.A6 USB.B6 | length 2118.2
  Top Layer w8: CN5.30@-1639,300 -1590.53,348.47 -1499.38,348.47 -1471.74,376.11 -1471.74,426.15 -1331.19,566.7 -1237.18,566.7 U18.71@-1128.06,457.58 -1084.73,414.25 v1@-1050.88,414.25 ; v1(-1006.23,993.26) -960,1039.49 -960,1239.63 -819.53,1380.1 -819.53,1504.53 ; USB.B6@-819.53,1551.92 -819.53,1504.53 ; USB.A6@-780.16,1551.92 -780.16,1506.84 -789,1498 -813,1498 -819.53,1504.53
  Bottom Layer w8: v1@-1056.64,413.84 -1056.64,942.85 v1(-1006.23,993.26)
  other v1: -1055,412
PA13: CN5.29 R37.2 U18.72 | length 648.6
  Top Layer w8: CN5.29@-1529,300 -1519.23,309.77 -1499.02,309.77 -1455.74,353.05 -1455.74,410.42 -1323.88,542.28 -1240.6,542.28 U18.72@-1141.98,443.66
  Bottom Layer w8: CN5.29@-1529,300 -1445.09,300 R37.2@-1443.09,298
PA14: CN5.25 R39.2 U18.76 | length 533
  Top Layer w8: CN5.25@-1539,100 -1536.11,102.89 -1396.45,102.89 U18.76@-1183.74,315.61
  Bottom Layer w8: CN5.25@-1529,100 -1449.09,100 R39.2@-1443.09,94
PA15: CN5.24 U18.77 | length 606.5
  Top Layer w8: CN5.24@-1639,0 -1590,49 -1422.51,49 U18.77@-1169.82,301.69
  Bottom Layer w8: CN5.24@-1629,0 CN5.24@-1629,12.31
PB0: CN4.35 R52.1 U18.35 | length 880
  Top Layer w8: U18.35@-554.58,527.18 -433.26,648.5 -249.56,648.5 -153.57,552.51 -51.42,552.51 -3.93,600 CN4.35@0,600
  Bottom Layer w8: R52.1@-195,550 -50,550 CN4.35@0,600
PB1: CN4.36 R50.1 U18.36 | length 647.9
  Top Layer w8: U18.36@-568.5,541.1 -437.2,672.41 -216.09,672.41 -153.45,609.77 -109.77,609.77 CN4.36@-100,600
  Bottom Layer w8: R50.1@-195,600 CN4.36@-100,600
PB2: CN4.37 R42.1 U18.37 | length 908.4
  Top Layer w8: U18.37@-582.43,555.02 -444.22,693.22 -185.94,693.22 -143.37,650.65 -45.48,650.65 0,696.13 CN4.37@0,700
  Bottom Layer w8: R42.1@-188.5,694 -188.12,694.38 -186.62,694.38 -138,743 -40,743 0,703 CN4.37@0,700
PB3: CN5.12 U18.89 | length 1122.7
  Top Layer w8: CN5.12@-1639,-600 -1637,-602 -1609,-602 -1554.42,-547.42 -1376.73,-547.42 -1264.16,-434.84 -1264.16,-126.71 U18.89@-1002.79,134.66
PB4: CN5.11 U18.90 | length 1040.9
  Top Layer w8: CN5.11@-1529,-600 -1364.41,-600 -1248.16,-483.75 -1248.16,-138.55 U18.90@-988.86,120.74
PB5: CN5.10 U18.91 | length 1219.1
  Top Layer w8: CN5.10@-1639,-700 -1597.47,-658.47 -1363.27,-658.47 -1232.16,-527.36 -1232.16,-150.4 U18.91@-974.94,106.82
PB6: CN5.9 U18.92 | length 1129.5
  Top Layer w8: CN5.9@-1539,-700 -1373.16,-700 -1214.41,-541.25 -1214.41,-160.49 U18.92@-961.03,92.9
PB7: CN5.8 U18.93 | length 1279.7
  Top Layer w8: CN5.8@-1638.74,-799.74 -1597.47,-799.74 -1541.97,-744.24 -1387.28,-744.24 -1198.41,-555.37 -1198.41,-172.33 -947.87,78.21 U18.93@-947.1,78.21
PB8: CN5.6 U18.95 | length 1356.4
  Top Layer w8: CN5.6@-1639,-900 -1639,-890 -1603.3,-854.3 -1420.41,-854.3 -1160.44,-594.33 -1160.44,-190.04 U18.95@-919.26,51.14
PB9: CN5.5 U18.96 | length 1292.6
  Top Layer w8: CN5.5@-1539,-900 -1503.16,-935.84 -1466.89,-935.84 -1144.44,-613.39 -1144.44,-201.87 U18.96@-905.35,37.22
PB10: CN4.47 R49.1 U18.47 | length 1183.6
  Top Layer w8: U18.47@-721.62,694.22 -524.32,891.51 -298.63,891.51 -223.7,966.44 -223.7,1046.35 -117.05,1153 -47,1153 CN4.47@0,1200
  Bottom Layer w8: R49.1@-185,1150 -50,1150 CN4.47@0,1200
PB11: CN4.48 U18.48 | length 893.3
  Top Layer w8: U18.48@-735.54,708.13 -534.84,908.82 -318.17,908.82 -241.29,985.7 -241.29,1077.85 -128.91,1190.23 -109.77,1190.23 CN4.48@-100,1200
PB12: CN5.50 U18.51 | length 1120.3
  Top Layer w8: CN5.50@-1639,1300 -1592.27,1346.73 -1492.68,1346.73 -1431.6,1285.64 -1431.6,1185.63 -1290.95,1044.99 -1158.69,1044.99 U18.51@-849.67,735.97
PB13: CN5.49 U18.52 | length 920.2
  Top Layer w8: CN5.49@-1529,1300 -1515.18,1300 -1501.01,1285.82 -1500.45,1285.82 -1450.57,1235.94 -1450.57,1173.57 -1302.88,1025.88 -1167.42,1025.88 U18.52@-878.53,737
PB14: CN5.48 U18.53 | length 1029.4
  Top Layer w8: CN5.48@-1639,1200 -1587.41,1251.59 -1517.96,1251.59 -1478.08,1211.71 -1478.08,1175.08 -1303.63,1000.63 -1170.01,1000.63 U18.53@-877.51,708.13
PB15: CN5.47 U18.54 | length 851.5
  Top Layer w8: CN5.47@-1533.45,1200 -1309.7,976.25 -1173.46,976.25 U18.54@-891.42,694.22
PC0: CN4.15 U18.15 | length 955.1
  Top Layer w8: U18.15@-568.5,176.42 -360.03,-32.06 -360.03,-209.45 -116.48,-453 -53,-453 CN4.15@0,-400
PC1: CN4.16 U18.16 | length 800.4
  Top Layer w8: U18.16@-554.58,190.34 -344.03,-20.21 -344.03,-193.05 -145.11,-391.98 -108.02,-391.98 CN4.16@-100,-400
PC2: CN4.17 U18.17 | length 888.8
  Top Layer w8: U18.17@-540.66,204.25 -540.66,202.66 -539.07,202.66 -328.03,-8.38 -328.03,-175.81 -155.2,-348.64 -48.64,-348.64 CN4.17@0,-300
PC3: CN4.18 U18.18 | length 732.1
  Top Layer w8: U18.18@-526.74,218.18 -312.03,3.47 -312.03,-151.47 -167.62,-295.87 -104.13,-295.87 CN4.18@-100,-300
PC4: CN4.33 U18.33 | length 649.9
  Top Layer w8: U18.33@-526.56,499.34 -428.23,597.66 -277.32,597.66 -128.77,449.11 -57.52,449.11 -6.64,500 CN4.33@0,500
PC5: CN4.34 U18.34 | length 539
  Top Layer w8: U18.34@-540.66,513.26 -428.65,625.33 -271.51,625.33 -160.03,513.85 -127.67,513.85 -113.82,500 CN4.34@-100,500
PC6: CN5.38 U18.63 | length 726.8
  Top Layer w8: CN5.38@-1629,700 -1623.33,700 -1572.45,750.87 -1496.71,750.87 -1474.9,772.68 -1220.45,772.68 U18.63@-1016.7,568.94
PC7: CN5.37 U18.64 | length 599.1
  Top Layer w8: CN5.37@-1529,700 -1515.18,700 -1500.81,714.37 -1500.64,714.37 -1465.64,749.38 -1224.37,749.38 U18.64@-1030.62,555.63
PC8: CN5.36 U18.65 | length 727
  Top Layer w8: CN5.36@-1639,600 -1639,604.92 -1600.76,643.16 -1517.84,643.16 -1433.89,727.11 -1230.55,727.11 U18.65@-1044.54,541.1
PC9: CN5.35 U18.66 | length 590.9
  Top Layer w8: CN5.35@-1529,600 -1515.55,600 -1408.26,707.29 -1236.35,707.29 -1058.46,529.41 U18.66@-1058.46,527.18
PC10: CN5.23 U18.78 | length 502.3
  Top Layer w8: CN5.23@-1539,0 -1443.67,0 U18.78@-1155.9,287.77
PC11: CN5.22 U18.79 | length 653.6
  Top Layer w8: CN5.22@-1639,-100 -1639,-97 -1636,-97 -1593,-54 -1469.84,-54 U18.79@-1141.98,273.86
PC12: CN5.21 U18.80 | length 560
  Top Layer w8: CN5.21@-1539,-100 -1487.99,-100 U18.80@-1128.06,259.93
PC13: CN4.7 U18.7 | length 2177.2
  Top Layer w8: U18.7@-679.86,65.06 -611.22,-3.58 -611.22,-136.74 -755.43,-280.95 -879.75,-280.95 -961.55,-362.75 -961.55,-785.91 -822.98,-924.49 -195.1,-924.49 -118.69,-848.08 -32.17,-848.08 -13.41,-829.32 -13.41,-827.23 0,-813.82 CN4.7@0,-800
PC14: R44.1 R66.1 U18.8 | length 704.1
  Top Layer w8: R66.1@-881.77,-383.92 -825.57,-383.92 R44.1@-825.5,-383.85 -825.5,-340.8 -808.1,-323.4 -717.9,-323.4 -586.17,-191.67 -586.17,-0.79 U18.8@-665.94,78.98
PC15: R45.1 R67.1 U18.9 | length 677.8
  Top Layer w8: R67.1@-711.1,-384.4 -711.25,-384.25 R45.1@-768,-384.25 -768,-350.2 -757.2,-339.4 -709.7,-339.4 -570.17,-199.87 -570.17,11.05 U18.9@-652.02,92.9
PD0: CN5.20 U18.81 | length 709.6
  Top Layer w8: CN5.20@-1639,-200 -1629.23,-190.23 -1599.32,-190.23 -1551.09,-142 -1502.16,-142 U18.81@-1114.14,246.02
PD1: CN5.19 U18.82 | length 657.4
  Top Layer w8: CN5.19@-1539,-200 -1464.6,-200 -1392.5,-127.9 -1392.5,-60.19 U18.82@-1100.22,232.09
PD2: CN5.18 U18.83 | length 828.8
  Top Layer w8: CN5.18@-1639,-300 -1638.74,-299.74 -1597.47,-299.74 -1545.84,-248.12 -1447.69,-248.12 -1368.16,-168.59 -1368.16,-63.68 U18.83@-1086.3,218.18
PD3: CN5.17 U18.84 | length 759.2
  Top Layer w8: CN5.17@-1539,-300 -1433.77,-300 -1350.82,-217.05 -1350.82,-74.18 U18.84@-1072.38,204.25
PD4: CN5.16 U18.85 | length 915.5
  Top Layer w8: CN5.16@-1638.74,-399.74 -1628.74,-399.74 -1575.62,-346.62 -1440.47,-346.62 -1333.15,-239.3 -1333.15,-84.35 U18.85@-1058.46,190.34
PD5: CN5.15 U18.86 | length 838.1
  Top Layer w8: CN5.15@-1539,-400 -1441.9,-400 -1317.15,-275.26 -1317.15,-96.2 U18.86@-1044.54,176.42
PD6: CN5.14 U18.87 | length 1002.4
  Top Layer w8: CN5.14@-1639,-500 -1638.74,-499.74 -1597.47,-499.74 -1547.36,-449.63 -1438.58,-449.63 -1299.06,-310.11 -1299.06,-105.93 U18.87@-1030.63,162.5
PD7: CN5.13 U18.88 | length 934.5
  Top Layer w8: CN5.13@-1538.28,-499.28 -1417.98,-499.28 -1283.06,-364.36 -1283.06,-117.54 -1176.32,-10.8 -1176.08,-10.8 U18.88@-1016.7,148.58
PD8: CN5.46 U18.55 | length 951.8
  Top Layer w8: CN5.46@-1639,1100 -1639,1109.65 -1602.05,1146.6 -1514.6,1146.6 -1318,950 -1175.05,950 U18.55@-905.35,680.29
PD9: CN5.45 U18.56 | length 785.5
  Top Layer w8: CN5.45@-1529.23,1090.23 -1505.42,1090.23 -1501.73,1086.55 -1499.72,1086.55 -1345.18,932 -1185,932 -919.38,666.38 U18.56@-919.26,666.38
PD10: CN5.44 U18.57 | length 889.2
  Top Layer w8: CN5.44@-1639,1001.35 -1592.12,1048.23 -1498.08,1048.23 -1361.31,911.46 -1192.2,911.46 U18.57@-933.19,652.45
PD11: CN5.43 U18.58 | length 742.6
  Top Layer w8: CN5.43@-1538.62,999.62 -1532.44,993.44 -1492.83,993.44 -1389.06,889.66 -1195.66,889.66 -1081.65,775.65 -1081.65,773.08 U18.58@-947.1,638.54
PD12: CN5.42 U18.59 | length 826.4
  Top Layer w8: CN5.42@-1639,900 -1629.27,900 -1587.75,941.53 -1486.59,941.53 -1411.81,866.74 -1203.15,866.74 U18.59@-961.03,624.62
PD13: CN5.41 U18.60 | length 674.6
  Top Layer w8: CN5.41@-1529,900 -1480.66,900 -1426.4,845.74 -1208.74,845.74 -974.94,611.94 U18.60@-974.94,610.7
PD14: CN5.40 U18.61 | length 770
  Top Layer w8: CN5.40@-1639,800 -1595.91,843.09 -1473.09,843.09 -1450.96,820.96 -1213.04,820.96 U18.61@-988.86,596.78
PD15: CN5.39 U18.62 | length 616.2
  Top Layer w8: CN5.39@-1529,800 -1527.97,798.97 -1218.89,798.97 U18.62@-1002.78,582.86
PE0: CN5.4 U18.97 | length 1411.9
  Top Layer w8: CN5.4@-1638.74,-999.74 -1597.47,-999.74 -1553.64,-955.91 -1459.58,-955.91 -1128.44,-624.77 -1128.44,-213.71 U18.97@-891.42,23.3
PE1: CN5.3 U18.98 | length 1323.8
  Top Layer w8: CN5.3@-1539,-1000 -1470.03,-1000 -1112.44,-642.41 -1112.44,-225.55 U18.98@-877.51,9.38
PE2: CN4.1 U18.1 | length 2250.2
  Top Layer w8: U18.1@-763.37,-18.46 -721.75,-60.08 -721.75,-107.37 -797.33,-182.95 -921.6,-182.95 -1060.44,-321.79 -1060.44,-827.94 -865.89,-1022.49 -243.25,-1022.49 -120.73,-1145 -45,-1145 CN4.1@0,-1100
